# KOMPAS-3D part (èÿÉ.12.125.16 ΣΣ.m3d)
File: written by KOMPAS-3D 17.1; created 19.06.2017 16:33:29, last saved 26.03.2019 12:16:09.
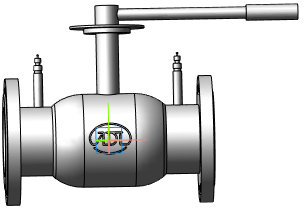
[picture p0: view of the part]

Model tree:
1. Операция без истории:2  (labels: Сталь 20  ГОСТ 1050-88)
